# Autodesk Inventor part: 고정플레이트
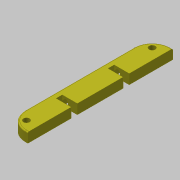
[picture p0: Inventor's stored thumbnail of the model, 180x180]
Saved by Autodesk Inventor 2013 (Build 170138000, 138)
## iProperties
Created: 2018-08
Part Number: 고정플레이트
Material: ABS 플라스틱
Document SubType Name: Modeling
Designer: mduedu
Density: 1 g/cm^3
Author: mduedu
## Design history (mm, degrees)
sketch "스케치1"
  geometry: L1 (0, -60)-(17, -60); L2 (17, -60)-(17, 60); L3 (17, 60)-(0, 60); L4 (0, 60)-(0, -60); 2 further points
  constraints: 8 end point, 2 parallel, 1 coincident, 1 horizontal, 1 midpoint, 1 perpendicular
  dimensions: "d0" = 120 distance between parallel lines of L3 L1; "d2" = 17 distance of L1.start L1.end
extrude "돌출1" new body sketch "스케치1" distance "d3" = 8; taper "d4" = 0 deg
fillet "모깎기1" dims "d5" = 15
fillet "모깎기2" dims "d6" = 1
sketch "스케치2"
  geometry: L1 (-17, 0)-(-17, 7) reference; L2 (0, 0)-(-17, 0) reference; L3 (-12.5, 4)-(-12.5, 0); L4 (-7.5, 4)-(-7.5, 0); A1 r 2.5 centre (-10, 4) between (-12.5, 4) and (-7.5, 4)
  constraints: 4 end point, 2 perpendicular, 2 point on circle, 2 point on line, 2 tangent, 1 centre point
  dimensions: "d7" = 5 diameter of A1; "d8" = 7 distance from line of A1.centre L1; "d9" = 4 distance from line of L2 A1.centre
extrude "돌출2" cut sketch "스케치2" stored distance "d10" = 70; taper "d11" = 0 deg
fillet "모깎기3" dims "d12" = 2.5
sketch "스케치3"
  geometry: L1 (-12.5, -19)-(0, -19); L2 (0, -19)-(0, -24); L3 (0, -24)-(-12.5, -24); L4 (-12.5, -24)-(-12.5, -19); L5 (0, -59)-(0, 59) reference; L6 (-17, 45)-(-17, -45) reference; 2 further points
  constraints: 8 end point, 2 parallel, 1 horizontal, 1 midpoint, 1 perpendicular, 1 vertical alignment
  dimensions: "d13" = 4.5 distance between parallel lines of L4 L6; "d14" = 19 distance from line of L1 point (0, 0); "d15" = 5 distance of L1.end L2.end
extrude "돌출3" cut sketch "스케치3" stored distance "d16" = 70; taper "d17" = 0 deg
sketch "스케치4"
  geometry: A1 r 15 centre (-2, -45) between (-17, -45) and (-2, -60) reference; A2 r 15 centre (-2, 45) between (-2, 60) and (-17, 45) reference; A3 r 10 centre (-2, 45) between (-2, 55) and (-12, 45); A4 r 10 centre (-2, -45) between (-12, -45) and (-2, -55); 3 further points
  constraints: 6 point on circle, 2 centre point, 2 horizontal alignment, 2 vertical alignment
  dimensions: "d18" = 5 radial gap between concentric circles of A3 A2; "d19" = 5 radial gap between concentric circles of A1 A4
hole "구멍1" sketch "스케치4" at (-9.071, 52.071), (-9.071, -52.071) diameter "d20" = 5; stored, may be unused: countersink angle "d24" = 90 deg, drill point angle "d26" = 118 deg; dims "d21" = 6, "d22" = 4, "d23" = 2, "d25" = 8
node "솔리드1"
mirror "대칭1"
